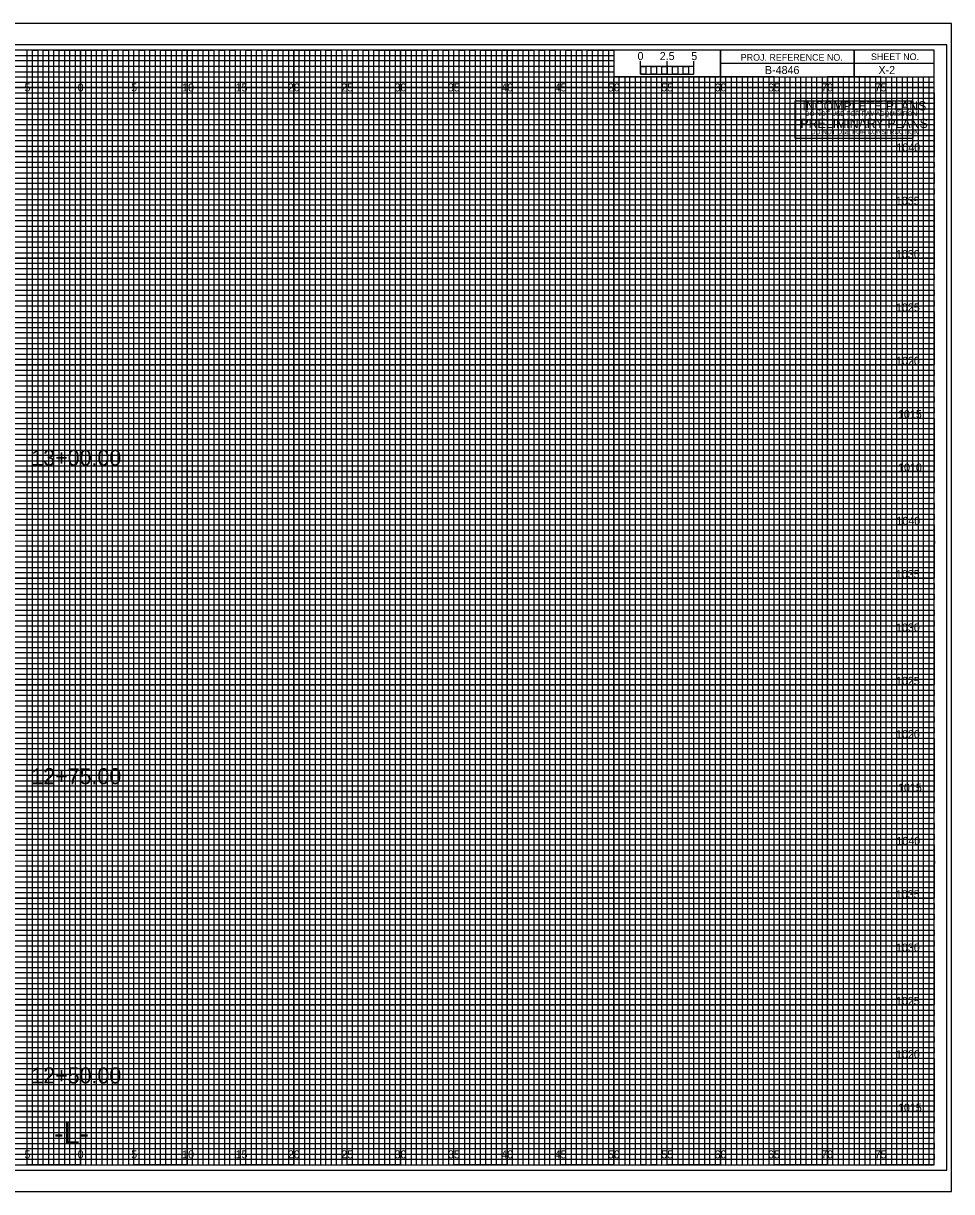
# Model space of a CAD drawing. Extents: x -7 to 162, y -2 to 987.
# Drawn here: x 74.6 to 161.7, y 107.5 to 217 of the extents above; entities that cross this region are included whole.
import ezdxf

# ---------------------------------------------------------------- set-up
doc = ezdxf.new("R2010")
doc.units = 0
for name, color, linetype in [('Default', 7, 'Continuous'), ('Exist Cross Section Cell', 7, 'Continuous'), ('Exist XS Center Line Elevation Label', 7, 'Continuous'), ('Exist XS Ground Line', 7, 'Continuous'), ('Prop CMT Concrete Structures', 7, 'Continuous'), ('Prop CMT DNC', 7, 'Continuous'), ('Prop CMT Guardrail Graphics', 7, 'Continuous'), ('Prop CMT Guardrail Widen Shoulder', 7, 'Continuous'), ('Prop CMT Pvmt Course 1', 7, 'Continuous'), ('Prop CMT Pvmt Surface', 7, 'Continuous'), ('Prop CMT Pvmt Surface Shoulder', 7, 'Continuous'), ('Prop CMT Shld Paved Course 1', 7, 'Continuous'), ('Prop CMT Shoulder Point', 7, 'Continuous'), ('Prop CMT Slope Grass', 7, 'Continuous'), ('Prop CMT Subgrade Earthwork', 7, 'Continuous'), ('Prop XS SE Text', 7, 'Continuous'), ('Prop XS Side Slope Text', 7, 'Continuous'), ('Typical Text Label CELL', 7, 'Continuous')]:
    doc.layers.add(name, color=color, linetype=linetype)

msp = doc.modelspace()

# ---------------------------------------------------------------- linework, layer by layer
at = {"layer": 'Default'}
for points in [[(146.99, 207.97), (146.99, 209.73), (158.01, 209.73), (158.01, 207.97)], [(146.99, 206.2), (146.99, 207.97), (158.01, 207.97), (158.01, 206.2)]]:
    msp.add_lwpolyline(points, close=True, dxfattribs=at)
at = {"layer": 'Exist XS Center Line Elevation Label'}
for points in [[(72.5, 110), (77.5, 110), (77.5, 214.5), (82.5, 214.5), (82.5, 110), (87.5, 110), (87.5, 214.5), (92.5, 214.5), (92.5, 110), (97.5, 110), (97.5, 214.5), (102.5, 214.5), (102.5, 110), (107.5, 110), (107.5, 214.5), (112.5, 214.5), (112.5, 110), (117.5, 110), (117.5, 214.5), (122.5, 214.5), (122.5, 110), (127.5, 110), (127.5, 214.5), (129.97, 214.5), (130, 214.5), (130, 212), (132.5, 212), (132.5, 110), (137.5, 110), (137.5, 212), (142.5, 212), (142.5, 110), (147.5, 110), (147.5, 212), (152.5, 212), (152.5, 110), (157.5, 110), (157.5, 212)], [(0, 212), (137.5, 212)], [(0, 202.5), (160, 202.5), (160, 207.5), (0, 207.5)], [(0, 192.5), (160, 192.5), (160, 197.5), (0, 197.5)], [(0, 182.5), (160, 182.5), (160, 187.5), (0, 187.5)], [(0, 172.5), (160, 172.5), (160, 177.5), (0, 177.5)], [(0, 162.5), (160, 162.5), (160, 167.5), (0, 167.5)], [(0, 152.5), (160, 152.5), (160, 157.5), (0, 157.5)], [(0, 142.5), (160, 142.5), (160, 147.5), (0, 147.5)], [(0, 132.5), (160, 132.5), (160, 137.5), (0, 137.5)], [(0, 122.5), (160, 122.5), (160, 127.5), (0, 127.5)], [(0, 112.5), (160, 112.5), (160, 117.5), (0, 117.5)]]:
    msp.add_lwpolyline(points, dxfattribs=at)
at = {"layer": 'Exist XS Ground Line'}
for p, q in [((75, 214.5), (70, 214.5)), ((75, 110), (75, 214.5)), ((85, 214.5), (80, 214.5)), ((80, 214.5), (80, 110)), ((85, 110), (85, 214.5)), ((95, 214.5), (90, 214.5)), ((90, 214.5), (90, 110)), ((95, 110), (95, 214.5)), ((105, 214.5), (100, 214.5)), ((100, 214.5), (100, 110)), ((105, 110), (105, 214.5)), ((115, 214.5), (110, 214.5)), ((110, 214.5), (110, 110)), ((115, 110), (115, 214.5)), ((125, 214.5), (120, 214.5)), ((120, 214.5), (120, 110)), ((125, 110), (125, 214.5)), ((130, 214.5), (130, 110)), ((135, 110), (135, 212)), ((145, 212), (140, 212)), ((140, 212), (140, 110)), ((145, 110), (145, 212)), ((155, 212), (150, 212)), ((150, 212), (150, 110)), ((155, 110), (155, 212)), ((80, 110), (75, 110)), ((90, 110), (85, 110)), ((100, 110), (95, 110)), ((110, 110), (105, 110)), ((120, 110), (115, 110)), ((130, 110), (125, 110)), ((140, 110), (135, 110)), ((150, 110), (145, 110)), ((160, 110), (155, 110)), ((160, 110), (160, 110))]:
    msp.add_line(p, q, dxfattribs=at)
for points in [[(0, 210), (160, 210), (160, 205), (0, 205)], [(0, 200), (160, 200), (160, 195), (0, 195)], [(0, 190), (160, 190), (160, 185), (0, 185)], [(0, 180), (160, 180), (160, 175), (0, 175)], [(0, 170), (160, 170), (160, 165), (0, 165)], [(0, 160), (160, 160), (160, 155), (0, 155)], [(0, 150), (160, 150), (160, 145), (0, 145)], [(0, 140), (160, 140), (160, 135), (0, 135)], [(0, 130), (160, 130), (160, 125), (0, 125)], [(0, 120), (160, 120), (160, 115), (0, 115)]]:
    msp.add_lwpolyline(points, dxfattribs=at)
at = {"layer": 'Prop CMT Concrete Structures'}
for p, q in [((75, 110), (75, 214.5)), ((80, 110), (80, 214.5)), ((85, 110), (85, 214.5)), ((90, 110), (90, 214.5)), ((95, 110), (95, 214.5)), ((100, 110), (100, 214.5)), ((105, 110), (105, 214.5)), ((110, 110), (110, 214.5)), ((115, 110), (115, 214.5)), ((120, 110), (120, 214.5)), ((125, 110), (125, 214.5)), ((130, 110), (130, 211.84)), ((135, 110), (135, 211.84)), ((140, 110), (140, 211.84)), ((145, 110), (145, 211.84)), ((150, 110), (150, 211.84)), ((155, 110), (155, 211.84)), ((0, 210), (160, 210)), ((0, 205), (160, 205)), ((0, 200), (160, 200)), ((0, 195), (160, 195)), ((0, 190), (160, 190)), ((0, 185), (160, 185)), ((0, 180), (160, 180)), ((0, 175), (160, 175)), ((0, 170), (160, 170)), ((0, 165), (160, 165)), ((0, 160), (160, 160)), ((0, 155), (160, 155)), ((0, 150), (160, 150)), ((0, 145), (160, 145)), ((0, 140), (160, 140)), ((0, 135), (160, 135)), ((0, 130), (160, 130)), ((0, 125), (160, 125)), ((0, 120), (160, 120)), ((0, 115), (160, 115))]:
    msp.add_line(p, q, dxfattribs=at)
at = {"layer": 'Prop CMT Guardrail Widen Shoulder'}
for p, q in [((161.65, 217), (-6.7, 217)), ((-6.7, 107.5), (161.65, 107.5))]:
    msp.add_line(p, q, dxfattribs=at)
at = {"layer": 'Prop CMT Pvmt Course 1'}
msp.add_lwpolyline([(-6.7, 107.5), (161.65, 107.5), (161.65, 217), (-6.7, 217)], close=True, dxfattribs=at)
at = {"layer": 'Prop CMT Pvmt Surface'}
for p, q in [((133.5, 212), (133, 212)), ((133, 212), (133, 110)), ((133.5, 110), (133.5, 212)), ((134.5, 212), (134, 212)), ((134, 212), (134, 110)), ((134.5, 110), (134.5, 212)), ((133, 110), (132.5, 110)), ((134, 110), (133.5, 110))]:
    msp.add_line(p, q, dxfattribs=at)
for points in [[(75, 110), (75.5, 110), (75.5, 214.5), (76, 214.5), (76, 110)], [(76, 110), (76.5, 110), (76.5, 214.5), (77, 214.5), (77, 110)], [(77.5, 110), (78, 110), (78, 214.5), (78.5, 214.5), (78.5, 110)], [(78.5, 110), (79, 110), (79, 214.5), (79.5, 214.5), (79.5, 110)], [(80, 110), (80.5, 110), (80.5, 214.5), (81, 214.5), (81, 110)], [(81, 110), (81.5, 110), (81.5, 214.5), (82, 214.5), (82, 110)], [(82.5, 110), (83, 110), (83, 214.5), (83.5, 214.5), (83.5, 110)], [(83.5, 110), (84, 110), (84, 214.5), (84.5, 214.5), (84.5, 110)], [(85, 110), (85.5, 110), (85.5, 214.5), (86, 214.5), (86, 110)], [(86, 110), (86.5, 110), (86.5, 214.5), (87, 214.5), (87, 110)], [(87.5, 110), (88, 110), (88, 214.5), (88.5, 214.5), (88.5, 110)], [(88.5, 110), (89, 110), (89, 214.5), (89.5, 214.5), (89.5, 110)], [(90, 110), (90.5, 110), (90.5, 214.5), (91, 214.5), (91, 110)], [(91, 110), (91.5, 110), (91.5, 214.5), (92, 214.5), (92, 110)], [(92.5, 110), (93, 110), (93, 214.5), (93.5, 214.5), (93.5, 110)], [(93.5, 110), (94, 110), (94, 214.5), (94.5, 214.5), (94.5, 110)], [(95, 110), (95.5, 110), (95.5, 214.5), (96, 214.5), (96, 110)], [(96, 110), (96.5, 110), (96.5, 214.5), (97, 214.5), (97, 110)], [(97.5, 110), (98, 110), (98, 214.5), (98.5, 214.5), (98.5, 110)], [(98.5, 110), (99, 110), (99, 214.5), (99.5, 214.5), (99.5, 110)], [(100, 110), (100.5, 110), (100.5, 214.5), (101, 214.5), (101, 110)], [(101, 110), (101.5, 110), (101.5, 214.5), (102, 214.5), (102, 110)], [(102.5, 110), (103, 110), (103, 214.5), (103.5, 214.5), (103.5, 110)], [(103.5, 110), (104, 110), (104, 214.5), (104.5, 214.5), (104.5, 110)], [(105, 110), (105.5, 110), (105.5, 214.5), (106, 214.5), (106, 110)], [(106, 110), (106.5, 110), (106.5, 214.5), (107, 214.5), (107, 110)], [(107.5, 110), (108, 110), (108, 214.5), (108.5, 214.5), (108.5, 110)], [(108.5, 110), (109, 110), (109, 214.5), (109.5, 214.5), (109.5, 110)], [(110, 110), (110.5, 110), (110.5, 214.5), (111, 214.5), (111, 110)], [(111, 110), (111.5, 110), (111.5, 214.5), (112, 214.5), (112, 110)], [(112.5, 110), (113, 110), (113, 214.5), (113.5, 214.5), (113.5, 110)], [(113.5, 110), (114, 110), (114, 214.5), (114.5, 214.5), (114.5, 110)], [(115, 110), (115.5, 110), (115.5, 214.5), (116, 214.5), (116, 110)], [(116, 110), (116.5, 110), (116.5, 214.5), (117, 214.5), (117, 110)], [(117.5, 110), (118, 110), (118, 214.5), (118.5, 214.5), (118.5, 110)], [(118.5, 110), (119, 110), (119, 214.5), (119.5, 214.5), (119.5, 110)], [(120, 110), (120.5, 110), (120.5, 214.5), (121, 214.5), (121, 110)], [(121, 110), (121.5, 110), (121.5, 214.5), (122, 214.5), (122, 110)], [(122.5, 110), (123, 110), (123, 214.5), (123.5, 214.5), (123.5, 110)], [(123.5, 110), (124, 110), (124, 214.5), (124.5, 214.5), (124.5, 110)], [(125, 110), (125.5, 110), (125.5, 214.5), (126, 214.5), (126, 110)], [(126, 110), (126.5, 110), (126.5, 214.5), (127, 214.5), (127, 110)], [(127.5, 110), (128, 110), (128, 214.5), (128.5, 214.5), (128.5, 110)], [(128.5, 110), (129, 110), (129, 214.5), (129.5, 214.5), (129.5, 110)], [(130, 110), (130.5, 110), (130.5, 212), (131.01, 212), (131.01, 110)], [(131, 110), (131.5, 110), (131.5, 212), (132, 212), (132, 110)], [(135, 110), (135.49, 110), (135.49, 212), (136, 212), (136, 110)], [(136, 110), (136.5, 110), (136.5, 212), (137.03, 212), (137.03, 110)], [(137.5, 110), (138, 110), (138, 212), (138.5, 212), (138.5, 110)], [(138.5, 110), (139, 110), (139, 212), (139.5, 212), (139.5, 110)], [(140, 110), (140.5, 110), (140.5, 212), (141, 212), (141, 110)], [(141, 110), (141.5, 110), (141.5, 212), (142, 212), (142, 110)], [(142.5, 110), (143, 110), (143, 212), (143.5, 212), (143.5, 110)], [(143.5, 110), (144, 110), (144, 212), (144.5, 212), (144.5, 110)], [(145, 110), (145.5, 110), (145.5, 212), (146, 212), (146, 110)], [(146, 110), (146.5, 110), (146.5, 212), (147, 212), (147, 110)], [(147.5, 110), (148, 110), (148, 212), (148.5, 212), (148.5, 110)], [(148.5, 110), (149, 110), (149, 212), (149.5, 212), (149.5, 110)], [(150, 110), (150.5, 110), (150.5, 212), (151, 212), (151, 110)], [(151, 110), (151.5, 110), (151.5, 212), (152, 212), (152, 110)], [(152.5, 110), (153, 110), (153, 212), (153.5, 212), (153.5, 110)], [(153.5, 110), (154, 110), (154, 212), (154.5, 212), (154.5, 110)], [(155, 110), (155.5, 110), (155.5, 212), (156, 212), (156, 110)], [(156, 110), (156.5, 110), (156.5, 212), (157, 212), (157, 110)], [(157.5, 110), (158, 110), (158, 212), (158.5, 212), (158.5, 110)], [(158.5, 110), (159, 110), (159, 212), (159.5, 212), (159.5, 110)]]:
    msp.add_lwpolyline(points, dxfattribs=at)
at = {"layer": 'Prop CMT Pvmt Surface Shoulder'}
for p, q in [((132.5, 212.25), (132.5, 213.45)), ((132.5, 212.95), (132.5, 213.45)), ((135, 212.25), (135, 213.45)), ((137.5, 212.25), (137.5, 213.45)), ((137.5, 212.95), (137.5, 213.45))]:
    msp.add_line(p, q, dxfattribs=at)
for points in [[(137.5, 212.95), (132.5, 212.95), (132.5, 212.25), (137.5, 212.25)], [(132.5, 212.95), (133, 212.95), (133, 212.25), (132.5, 212.25)], [(133.5, 212.95), (134, 212.95), (134, 212.25), (133.5, 212.25)], [(134.5, 212.95), (135, 212.95), (135, 212.25), (134.5, 212.25)], [(135.5, 212.95), (136, 212.95), (136, 212.25), (135.5, 212.25)], [(136.5, 212.95), (137, 212.95), (137, 212.25), (136.5, 212.25)]]:
    msp.add_lwpolyline(points, close=True, dxfattribs=at)
at = {"layer": 'Prop CMT Shld Paved Course 1'}
for p, q in [((0, 214), (130, 214)), ((130, 214), (130, 213.49)), ((130, 213.49), (0, 213.49)), ((0, 213), (130, 213)), ((130, 212.44), (0, 212.44)), ((130, 213), (130, 212.44)), ((0, 211.5), (160, 211.5))]:
    msp.add_line(p, q, dxfattribs=at)
for points in [[(0, 211), (135, 211), (160, 211), (160, 211), (0, 211)], [(0, 210.5), (160, 210.5), (160, 209.5), (0, 209.5)], [(0, 209), (160, 209), (160, 208.5), (0, 208.49)], [(0, 208), (160, 208), (160, 207), (0, 207)], [(0, 206.5), (160, 206.5), (160, 206), (0, 206)], [(0, 205.5), (160, 205.5), (160, 204.5), (0, 204.5)], [(0, 204), (160, 204), (160, 203.5), (0, 203.5)], [(0, 203), (160, 203), (160, 202), (0, 202)], [(0, 201.5), (160, 201.5), (160, 201), (0, 201)], [(0, 200.5), (160, 200.5), (160, 199.5), (0, 199.5)], [(0, 199), (160, 199), (160, 198.5), (0, 198.5)], [(0, 198), (160, 198), (160, 196.97), (160, 196.5), (160, 196), (0, 196)], [(0, 197), (160, 197), (160, 196.5), (0, 196.5)], [(0, 195.5), (160, 195.5), (160, 194.5), (0, 194.52)], [(0, 194.52), (160, 194.5), (160, 194), (0, 194)], [(0, 193.5), (160, 193.5), (160, 193), (0, 193)], [(0, 192), (160, 192), (160, 191.5), (0, 191.5)], [(0, 191), (160, 191), (160, 190.5), (0, 190.5)], [(-0.04, 189.44), (160, 189.44), (160, 188.94), (-0.04, 188.94)], [(0, 188.5), (160, 188.5), (160, 188), (0, 188)], [(0, 187), (160, 187), (160, 186.5), (0, 186.5)], [(0, 186), (160, 186), (160, 185.5), (0, 185.5)], [(0, 184.5), (160, 184.5), (160, 184), (0, 184)], [(0, 183.5), (160, 183.5), (160, 183), (0, 183)], [(0, 182), (160, 182), (160, 181.5), (0, 181.5)], [(0, 181), (160, 181), (160, 180.5), (0, 180.5)], [(0, 179.5), (160, 179.5), (160, 178.99), (0, 179)], [(0, 178.5), (160, 178.5), (160, 178), (0, 178)], [(0, 177), (160, 177), (160, 176.5), (0, 176.5)], [(0, 176), (160, 176), (160, 175.5), (0, 175.5)], [(0, 174.5), (160, 174.5), (160, 174), (0, 174)], [(0, 173.5), (160, 173.5), (160, 173), (0, 173)], [(0, 172), (160, 172), (160, 171.5), (0, 171.5)], [(0, 171), (160, 171), (160, 170.5), (0, 170.5)], [(0, 169.5), (160, 169.5), (160, 169), (0, 169)], [(0, 168.5), (160.03, 168.46), (160, 168), (0, 168)], [(0, 167), (160, 167), (160, 166.5), (0, 166.5)], [(0, 166), (160, 166), (160, 165.5), (0, 165.5)], [(0, 164.5), (160, 164.5), (160, 164), (0, 164)], [(0, 163.5), (160, 163.5), (160, 163), (0, 163)], [(0, 162), (160, 162), (160, 161.5), (0, 161.5)], [(0, 161), (160, 161), (160, 160.5), (0, 160.5)], [(0, 159.5), (160, 159.5), (160, 159), (0, 159)], [(0, 158.5), (160, 158.5), (160, 158), (0, 158)], [(0, 157), (160, 157), (160, 156.5), (0, 156.5)], [(0, 156), (160, 156), (160, 155.5), (0, 155.5)], [(0, 154.5), (160, 154.5), (160, 154), (0, 154)], [(0, 153.5), (160, 153.5), (160, 153), (0, 153)], [(0, 152), (160, 152), (160, 151.5), (0, 151.5)], [(0, 151), (160, 151), (160, 150.5), (0, 150.5)], [(0, 149.5), (160, 149.5), (160, 148.99), (0, 149)], [(0, 148.5), (160, 148.5), (160, 148), (0, 148)], [(0, 147), (160, 147), (160, 146.5), (0, 146.5)], [(0, 146), (160, 146), (160, 145.5), (0, 145.5)], [(0, 144.5), (160, 144.5), (160, 144), (0, 144)], [(0, 143.5), (160, 143.5), (160, 143), (0, 143)], [(0, 142), (160, 142), (160, 141.5), (0, 141.5)], [(0, 141), (160, 141), (160, 140.5), (0, 140.5)], [(0, 139.5), (160, 139.5), (160, 139), (0, 139)], [(0, 138.5), (160.03, 138.46), (160, 138), (0, 138)], [(0, 137), (160, 137), (160, 136.5), (0, 136.5)], [(0, 136), (160, 136), (160, 135.5), (0, 135.5)], [(0, 134.5), (160, 134.5), (160, 134), (0, 134)], [(0, 133.5), (160, 133.5), (160, 133), (0, 133)], [(0, 132), (160, 132), (160, 131.5), (0, 131.5)], [(0, 131), (160, 131), (160, 130.5), (0, 130.5)], [(0, 129.5), (160, 129.5), (160, 129), (0, 129)], [(0, 128.5), (160, 128.5), (160, 128), (0, 128)], [(0, 127), (160, 127), (160, 126.5), (0, 126.5)], [(0, 126), (160, 126), (160, 125.5), (0, 125.5)], [(0, 124.5), (160, 124.5), (160, 124), (0, 124)], [(0, 123.5), (160, 123.5), (160, 123), (0, 123)], [(0, 122), (160, 122), (160, 121.5), (0, 121.5)], [(0, 121), (160, 121), (160, 120.5), (0, 120.5)], [(0, 119.5), (160, 119.5), (160, 119), (0, 119)], [(0, 118.5), (160, 118.5), (160, 118), (0, 118)], [(0, 117), (160, 117), (160, 116.5), (0, 116.5)], [(0, 116), (160, 116), (160, 115.5), (0, 115.5)], [(0, 114.5), (160, 114.5), (160, 114), (0, 114)], [(0, 113.5), (160, 113.5), (160, 113), (0, 113)], [(0, 112), (160, 112), (160, 111.5), (0, 111.5)], [(0, 111), (160, 111), (160, 110.5), (0, 110.5)]]:
    msp.add_lwpolyline(points, dxfattribs=at)
at = {"layer": 'Prop CMT Slope Grass'}
msp.add_lwpolyline([(-5.4, 109.5), (161.2, 109.5), (161.2, 215), (-5.4, 215)], close=True, dxfattribs=at)
at = {"layer": 'Prop CMT Subgrade Earthwork'}
for p, q in [((152.5, 214.5), (152.5, 212)), ((152.5, 212), (152.5, 214.5)), ((160, 213.25), (140, 213.25)), ((140, 213.25), (140, 212)), ((140, 212), (160, 212))]:
    msp.add_line(p, q, dxfattribs=at)
for points in [[(160, 214.5), (0, 214.5), (0, 110), (160, 110)], [(140, 214.5), (130, 214.5), (130, 212.02), (140, 212.02)], [(160, 214.5), (140, 214.5), (140, 212), (160, 212)]]:
    msp.add_lwpolyline(points, close=True, dxfattribs=at)

# ---------------------------------------------------------------- texts
at = {"layer": 'Default'}
for s, height, p in [('INCOMPLETE PLANS', 0.864, (147.66, 208.84)), ('PRELIMINARY PLANS', 0.864, (147.47, 207.19)), ('DO NOT USE FOR R/W ACQUISITION', 0.432, (147.9, 208.32)), ('DO NOT USE FOR CONSTRUCTION', 0.432, (148.46, 206.61))]:
    msp.add_text(s, height=height, dxfattribs=at).set_placement(p)
at = {"layer": 'Exist Cross Section Cell'}
for s, p in [('5', (74.74, 210.62)), ('0', (79.73, 210.62)), ('0', (79.73, 210.62)), ('5', (84.74, 210.62)), ('10', (89.52, 210.62)), ('15', (94.53, 210.62)), ('20', (99.43, 210.62)), ('25', (104.44, 210.62)), ('30', (109.43, 210.62)), ('35', (114.44, 210.62)), ('40', (119.43, 210.62)), ('45', (124.44, 210.62)), ('50', (129.43, 210.62)), ('55', (134.44, 210.62)), ('60', (139.43, 210.62)), ('65', (144.44, 210.62)), ('70', (149.43, 210.62)), ('75', (154.44, 210.62)), ('5', (74.74, 110.62)), ('0', (79.73, 110.62)), ('0', (79.73, 110.62)), ('5', (84.74, 110.62)), ('10', (89.52, 110.62)), ('15', (94.53, 110.62)), ('20', (99.43, 110.62)), ('25', (104.44, 110.62)), ('30', (109.43, 110.62)), ('35', (114.44, 110.62)), ('40', (119.43, 110.62)), ('45', (124.44, 110.62)), ('50', (129.43, 110.62)), ('55', (134.44, 110.62)), ('60', (139.43, 110.62)), ('65', (144.44, 110.62)), ('70', (149.43, 110.62)), ('75', (154.44, 110.62))]:
    msp.add_text(s, height=0.75, dxfattribs=at).set_placement(p)
at = {"layer": 'Prop CMT DNC'}
msp.add_text('-L-', height=2, dxfattribs=at).set_placement((77.53, 112))
at = {"layer": 'Prop CMT Guardrail Graphics'}
msp.add_text('B-4846', height=0.75, dxfattribs=at).set_placement((144.15, 212.25))
at = {"layer": 'Prop CMT Pvmt Surface Shoulder'}
msp.add_text('0', height=0.75, dxfattribs=at).set_placement((132.21, 213.56))
at = {"layer": 'Prop CMT Shoulder Point'}
for s, p in [('2.5', (134.29, 213.56)), ('5', (137.24, 213.56))]:
    msp.add_text(s, height=0.75, dxfattribs=at).set_placement(p)
at = {"layer": 'Prop CMT Subgrade Earthwork'}
for s, p in [('PROJ. REFERENCE NO.', (141.88, 213.5)), ('SHEET NO.', (154.09, 213.56))]:
    msp.add_text(s, height=0.625, dxfattribs=at).set_placement(p)
at = {"layer": 'Prop XS SE Text'}
msp.add_text('X-2', height=0.75, dxfattribs=at).set_placement((154.79, 212.25))
at = {"layer": 'Prop XS Side Slope Text'}
for s, p in [('13+00.00', (75.39, 175.54)), ('12+75.00', (75.39, 145.69)), ('12+50.00', (75.39, 117.64))]:
    msp.add_text(s, height=1.5, dxfattribs=at).set_placement(p)
at = {"layer": 'Typical Text Label CELL'}
for s, p in [('1040', (156.47, 205)), ('1035', (156.42, 200)), ('1030', (156.43, 195)), ('1025', (156.43, 190)), ('1020', (156.44, 185)), ('1015', (156.62, 180)), ('1010', (156.63, 175)), ('1040', (156.47, 170)), ('1035', (156.42, 165)), ('1030', (156.43, 160)), ('1025', (156.43, 155)), ('1020', (156.44, 150)), ('1015', (156.62, 145)), ('1040', (156.47, 140)), ('1035', (156.42, 135)), ('1030', (156.43, 130)), ('1025', (156.43, 125)), ('1020', (156.44, 120)), ('1015', (156.62, 115))]:
    msp.add_text(s, height=0.75, dxfattribs=at).set_placement(p)

doc.saveas('drawing.dxf')
